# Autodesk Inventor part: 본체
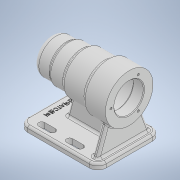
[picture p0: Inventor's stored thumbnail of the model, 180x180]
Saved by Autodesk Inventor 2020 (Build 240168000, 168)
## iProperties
Created: 2021-10
Part Number: 본체
Material: 일반
Document SubType Name: Modeling
Designer: user
Density: 1 g/cm^3
Appearance: 기본값
Author: user
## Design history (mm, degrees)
sketch "스케치1"
  geometry: L1 (0, 0)-(0, 27.861); L2 (0, 0)-(112, 0); L3 (112, 0)-(112, 34); L4 (112, 34)-(80, 34); L5 (80, 34)-(80, 30); L6 (80, 30)-(46, 30); L7 (46, 30)-(46, 27); L8 (46, 27)-(24, 27); L9 (24, 27)-(24, 25); L10 (24, 25)-(0, 25); L11 (0, 25)-(0, 0); 1 further point
  constraints: 22 end point, 8 perpendicular, 1 collinear, 1 horizontal, 1 vertical
  dimensions: "d0" = 112 distance between parallel lines of L3 L11; "d2" = 68 diameter of L4 L2; "d3" = 60 diameter of L6 L2; "d4" = 54 diameter of L8 L2; "d5" = 50 diameter of L10 L2; "d6" = 24 distance of L9.end L10.end; "d7" = 46 distance between parallel lines of L1 L7; "d8" = 80 distance between parallel lines of L1 L5
revolve "회전1" sketch "스케치1" stored, may be unused: angle "d9" = 90 deg
sketch "스케치2"
  geometry: C1 r 21 at (0, 0); 1 further point
  constraints: 1 centre point, 1 coincident
  dimensions: "d10" = 42 diameter of C1
extrude "돌출1" cut sketch "스케치2" distance "d11" = 15; taper "d12" = 0 deg
sketch "스케치3"
  geometry: C1 r 24 at (0, 0); 1 further point
  constraints: 1 centre point, 1 coincident
  dimensions: "d13" = 48 diameter of C1
extrude "돌출2" cut sketch "스케치3" distance "d14" = 54; taper "d15" = 0 deg
sketch "스케치4"
  geometry: C1 r 21 at (0, 0); 1 further point
  constraints: 1 centre point, 1 coincident
  dimensions: "d16" = 42 diameter of C1
extrude "돌출3" cut sketch "스케치4" distance "d17" = 12; taper "d18" = 0 deg
sketch "스케치5"
  geometry: C1 r 17.5 at (0, 0); 1 further point
  constraints: 1 centre point, 1 coincident
  dimensions: "d19" = 35 diameter of C1
extrude "돌출4" cut sketch "스케치5" distance "d20" = 18; taper "d21" = 0 deg
sketch "스케치6"
  geometry: C1 r 16 at (0, 0); 1 further point
  constraints: 1 centre point, 1 coincident
  dimensions: "d22" = 32 diameter of C1
extrude "돌출5" cut sketch "스케치6" distance "d23" = 4; taper "d24" = 0 deg
sketch "스케치7"
  geometry: C1 r 10.5 at (0, 0); 1 further point
  constraints: 1 centre point, 1 coincident
  dimensions: "d25" = 21 diameter of C1
extrude "돌출6" cut sketch "스케치7" distance "d26" = 3; taper "d27" = 0 deg
fillet "모깎기1" dims "d28" = 0.3
fillet "모깎기2" dims "d29" = 0.3
fillet "모깎기3" dims "d30" = 3
fillet "모깎기4" dims "d31" = 3
chamfer "모따기1" distance "d32" = 1; stored, may be unused: second distance "d33" = 2, angle "d34" = 45 deg
fillet "모깎기5" dims "d35" = 3
fillet "모깎기6" dims "d36" = 3
fillet "모깎기7" dims "d37" = 8
sketch "스케치11"
  geometry: L1 (0, 0)-(-26, 0); 1 further point
  constraints: 2 end point, 1 coincident, 1 horizontal
  dimensions: "d50" = 26 distance of L1.start L1.end
hole "구멍2" sketch "스케치11" at (-26, 0) diameter "d51" = 3.242; stored, may be unused: countersink angle "d55" = 90 deg, drill point angle "d57" = 118 deg; dims "d52" = 8, "d53" = 4, "d54" = 2, "d56" = 11
node "작업 평면2"
sketch "스케치12"
  geometry: L1 (0, 0)-(-56, 0); L2 (-112, -45)-(0, -45); L3 (0, -45)-(0, 45); L4 (0, 45)-(-112, 45); L5 (-112, 45)-(-112, -45); L6 (-112, -45)-(0, 45); L7 (0, -45)-(-112, 45)
  constraints: 14 end point, 2 horizontal, 2 midpoint, 2 parallel, 1 perpendicular
  dimensions: "d62" = 56 distance of L1.start L1.end; "d63" = 112 distance of L4.end L3.end; "d64" = 90 distance between parallel lines of L4 L2
extrude "돌출7" join sketch "스케치12" distance "d65" = 8; taper "d66" = 0 deg
fillet "모깎기8" dims "d67" = 12
fillet "모깎기9" dims "d68" = 3
sketch "스케치14"
  geometry: L1 (20, -33)-(35, -33); L2 (20, -37.5)-(35, -37.5); L3 (35, -28.5)-(20, -28.5); L4 (0, 33)-(0, -33) reference; L5 (60, -33)-(75, -33); L6 (60, -37.5)-(75, -37.5); L7 (75, -28.5)-(60, -28.5); A1 r 4.5 centre (20, -33) between (20, -28.5) and (20, -37.5); A2 r 4.5 centre (35, -33) between (35, -37.5) and (35, -28.5); A3 r 4.5 centre (60, -33) between (60, -28.5) and (60, -37.5); A4 r 4.5 centre (75, -33) between (75, -37.5) and (75, -28.5); 3 further points
  constraints: 16 end point, 8 point on circle, 8 tangent, 4 centre point, 2 horizontal, 2 midpoint, 2 parallel
  dimensions: "d69" = 15 distance of L1.start L1.end; "d70" = 20 distance from line of L4 L1.start; "d71" = 9 distance between parallel lines of L2 L3; "d72" = 33 vertical distance of point (0, 0) point (27.5, -33); "d75" = 15 distance of L5.end L5.start; "d76" = 25 distance of L5.start L1.end; "d77" = 9 distance between parallel lines of L6 L7; "d78" = 33 vertical distance of point (0, 0) point (67.5, -33)
extrude "돌출8" cut sketch "스케치14" extent not by distance; stored distance "d73" = 0; taper "d74" = 0 deg
sketch "스케치15"
  geometry: L1 (104, 37)-(96, 37); L2 (96, 37)-(96, -37); L3 (96, -37)-(104, -37); L4 (104, -37)-(104, 37); L5 (112, -33)-(112, 33) reference; L6 (12, -45)-(100, -45) reference; L7 (100, 45)-(12, 45) reference; L8 (27, 4)-(104, 4); L9 (104, 4)-(104, -4); L10 (104, -4)-(27, -4); L11 (27, -4)-(27, 4); 3 further points
  constraints: 16 end point, 4 parallel, 2 horizontal, 2 perpendicular
  dimensions: "d79" = 8 distance between parallel lines of L5 L4; "d80" = 8 distance between parallel lines of L4 L2; "d82" = 8 distance between parallel lines of L6 L3; "d83" = 8 distance between parallel lines of L7 L1; "d84" = 8 distance between parallel lines of L10 L8; "d85" = 8 distance between parallel lines of L5 L9; "d86" = 77 distance between parallel lines of L4 L11; "d87" = 4 distance from line of point (0, 0) L10
extrude "돌출9" join sketch "스케치15" stored distance "d88" = 10; taper "d89" = 0 deg
sketch "스케치16"
  geometry: L1 (-29, 0)-(37, 0) reference; L2 (-33.5, 0)-(-24.5, 0) reference; L3 (-38, 0)-(-29, 0) reference; L4 (-19.409, 37.342)-(-33, 0); L5 (-41, -3)-(-41, -8) reference; A1 r 34 centre (4, 62) between (8, 28.236) and (0, 28.236) reference; 1 further point
  constraints: 2 end point, 1 point on circle, 1 point on line
  dimensions: "d90" = 8 distance from line of L4.end L5; "d91" = 110 deg angle of L3 L4
feature "리브1" sketch "스케치16" dims "d92" = 1, "d93" = 8, "d94" = 0, "d95" = 0, "d96" = 1, "d97" = 1
feature "면 기울기1" dims angle "d98" = 15 deg
fillet "모깎기10" dims "d99" = 3
fillet "모깎기11" dims "d100" = 3
fillet "모깎기12" dims "d101" = 3
sketch "스케치17"
  geometry: L1 (0, 33)-(0, -33) reference; A1 r 4.5 centre (20, 33) between (20, 37.5) and (20, 28.5) reference; A2 r 4.5 centre (20, -33) between (20, -28.5) and (20, -37.5) reference; 2 further points
  constraints: 1 other
  dimensions: "d102" = 33 vertical distance of A1.centre point (12, 0); "d103" = 12 distance from line of L1 point (12, 0)
feature "엠보싱1" sketch "스케치17" dims "d104" = 0.5, "d105" = 0
node "솔리드1"
pattern_circular "원형 패턴1" dims angle "d59" = 360 deg
mirror "미러1"
mirror "미러2"
feature "A9D066F2-1C7D-4E18-AEED-F7BC21143FA4" dims "d51" = 3.242, "d52" = 8, "d53" = 4, "d54" = 2, "d55" = 90 deg, "d56" = 11, "d57" = 118 deg
